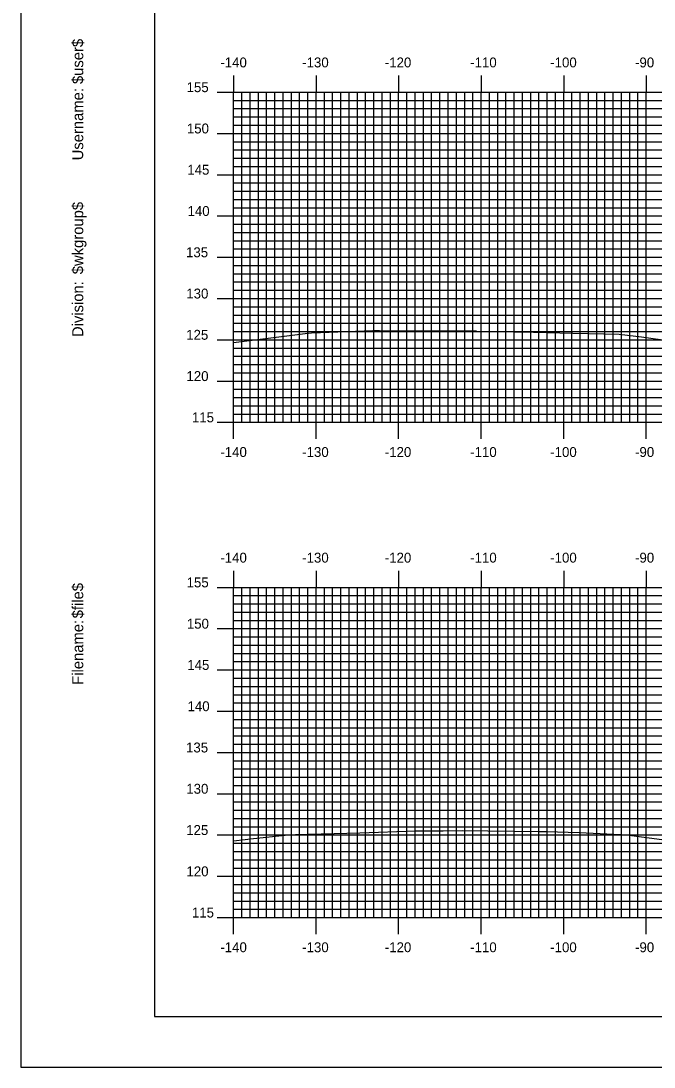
# Model space of a CAD drawing. Extents: x 854508 to 854851, y 364661 to 364881.
# Drawn here: x 854508 to 854584.8, y 364661.3 to 364788 of the extents above; entities that cross this region are included whole.
import ezdxf

# ---------------------------------------------------------------- set-up
doc = ezdxf.new("R2010")
doc.units = 0
for name, color, linetype in [('BORDER', 7, 'Continuous'), ('H_V ANNOTATION', 7, 'Continuous'), ('M_Roadway_Centerline', 7, 'Continuous'), ('MAJOR', 7, 'Continuous'), ('MINOR', 7, 'Continuous'), ('PLOT BOUNDARY', 7, 'Continuous'), ('S_Roadway_Centerline', 7, 'Continuous')]:
    doc.layers.add(name, color=color, linetype=linetype)

msp = doc.modelspace()

# ---------------------------------------------------------------- linework, layer by layer
at = {"layer": 'BORDER'}
msp.add_lwpolyline([(854524.23, 364667.37), (854844.23, 364667.37), (854844.23, 364877.37), (854524.23, 364877.37)], close=True, dxfattribs=at)
at = {"layer": 'MAJOR'}
for p, q in [((854533.83, 364781.37), (854533.83, 364779.37)), ((854543.83, 364781.37), (854543.83, 364779.37)), ((854553.83, 364781.37), (854553.83, 364779.37)), ((854563.83, 364781.37), (854563.83, 364779.37)), ((854573.83, 364781.37), (854573.83, 364779.37)), ((854583.83, 364781.37), (854583.83, 364779.37)), ((854531.83, 364779.37), (854533.83, 364779.37)), ((854533.83, 364779.37), (854813.83, 364779.37)), ((854533.83, 364739.37), (854533.83, 364779.37)), ((854533.83, 364739.37), (854533.83, 364779.37)), ((854533.83, 364779.37), (854813.83, 364779.37)), ((854543.83, 364739.37), (854543.83, 364779.37)), ((854553.83, 364739.37), (854553.83, 364779.37)), ((854563.83, 364739.37), (854563.83, 364779.37)), ((854573.83, 364739.37), (854573.83, 364779.37)), ((854583.83, 364739.37), (854583.83, 364779.37)), ((854531.83, 364774.37), (854533.83, 364774.37)), ((854533.83, 364774.37), (854813.83, 364774.37)), ((854531.83, 364769.37), (854533.83, 364769.37)), ((854533.83, 364769.37), (854813.83, 364769.37)), ((854531.83, 364764.37), (854533.83, 364764.37)), ((854533.83, 364764.37), (854813.83, 364764.37)), ((854531.83, 364759.37), (854533.83, 364759.37)), ((854533.83, 364759.37), (854813.83, 364759.37)), ((854531.83, 364754.37), (854533.83, 364754.37)), ((854533.83, 364754.37), (854813.83, 364754.37)), ((854531.83, 364749.37), (854533.83, 364749.37)), ((854533.83, 364749.37), (854813.83, 364749.37)), ((854531.83, 364744.37), (854533.83, 364744.37)), ((854533.83, 364744.37), (854813.83, 364744.37)), ((854531.83, 364739.37), (854533.83, 364739.37)), ((854533.83, 364739.37), (854813.83, 364739.37)), ((854533.83, 364739.37), (854813.83, 364739.37)), ((854533.83, 364737.37), (854533.83, 364739.37)), ((854543.83, 364737.37), (854543.83, 364739.37)), ((854553.83, 364737.37), (854553.83, 364739.37)), ((854563.83, 364737.37), (854563.83, 364739.37)), ((854573.83, 364737.37), (854573.83, 364739.37)), ((854583.83, 364737.37), (854583.83, 364739.37)), ((854533.83, 364721.37), (854533.83, 364719.37)), ((854543.83, 364721.37), (854543.83, 364719.37)), ((854553.83, 364721.37), (854553.83, 364719.37)), ((854563.83, 364721.37), (854563.83, 364719.37)), ((854573.83, 364721.37), (854573.83, 364719.37)), ((854583.83, 364721.37), (854583.83, 364719.37)), ((854531.83, 364719.37), (854533.83, 364719.37)), ((854533.83, 364719.37), (854813.83, 364719.37)), ((854533.83, 364679.37), (854533.83, 364719.37)), ((854533.83, 364679.37), (854533.83, 364719.37)), ((854533.83, 364719.37), (854813.83, 364719.37)), ((854543.83, 364679.37), (854543.83, 364719.37)), ((854553.83, 364679.37), (854553.83, 364719.37)), ((854563.83, 364679.37), (854563.83, 364719.37)), ((854573.83, 364679.37), (854573.83, 364719.37)), ((854583.83, 364679.37), (854583.83, 364719.37)), ((854531.83, 364714.37), (854533.83, 364714.37)), ((854533.83, 364714.37), (854813.83, 364714.37)), ((854531.83, 364709.37), (854533.83, 364709.37)), ((854533.83, 364709.37), (854813.83, 364709.37)), ((854531.83, 364704.37), (854533.83, 364704.37)), ((854533.83, 364704.37), (854813.83, 364704.37)), ((854531.83, 364699.37), (854533.83, 364699.37)), ((854533.83, 364699.37), (854813.83, 364699.37)), ((854531.83, 364694.37), (854533.83, 364694.37)), ((854533.83, 364694.37), (854813.83, 364694.37)), ((854531.83, 364689.37), (854533.83, 364689.37)), ((854533.83, 364689.37), (854813.83, 364689.37)), ((854531.83, 364684.37), (854533.83, 364684.37)), ((854533.83, 364684.37), (854813.83, 364684.37)), ((854531.83, 364679.37), (854533.83, 364679.37)), ((854533.83, 364679.37), (854813.83, 364679.37)), ((854533.83, 364679.37), (854813.83, 364679.37)), ((854533.83, 364677.37), (854533.83, 364679.37)), ((854543.83, 364677.37), (854543.83, 364679.37)), ((854553.83, 364677.37), (854553.83, 364679.37)), ((854563.83, 364677.37), (854563.83, 364679.37)), ((854573.83, 364677.37), (854573.83, 364679.37)), ((854583.83, 364677.37), (854583.83, 364679.37))]:
    msp.add_line(p, q, dxfattribs=at)
at = {"layer": 'MINOR'}
for p, q in [((854533.83, 364778.37), (854813.83, 364778.37)), ((854533.83, 364778.37), (854535.84, 364778.37)), ((854534.83, 364739.37), (854534.83, 364779.37)), ((854535.83, 364739.37), (854535.83, 364779.37)), ((854536.83, 364739.37), (854536.83, 364779.37)), ((854537.83, 364739.37), (854537.83, 364779.37)), ((854538.83, 364739.37), (854538.83, 364779.37)), ((854539.83, 364739.37), (854539.83, 364779.37)), ((854540.83, 364739.37), (854540.83, 364779.37)), ((854541.83, 364739.37), (854541.83, 364779.37)), ((854542.83, 364739.37), (854542.83, 364779.37)), ((854544.83, 364739.37), (854544.83, 364779.37)), ((854545.83, 364739.37), (854545.83, 364779.37)), ((854546.83, 364739.37), (854546.83, 364779.37)), ((854547.83, 364739.37), (854547.83, 364779.37)), ((854548.83, 364739.37), (854548.83, 364779.37)), ((854549.83, 364739.37), (854549.83, 364779.37)), ((854550.83, 364739.37), (854550.83, 364779.37)), ((854551.83, 364739.37), (854551.83, 364779.37)), ((854552.83, 364739.37), (854552.83, 364779.37)), ((854554.83, 364739.37), (854554.83, 364779.37)), ((854555.83, 364739.37), (854555.83, 364779.37)), ((854556.83, 364739.37), (854556.83, 364779.37)), ((854557.83, 364739.37), (854557.83, 364779.37)), ((854558.83, 364739.37), (854558.83, 364779.37)), ((854559.83, 364739.37), (854559.83, 364779.37)), ((854560.83, 364739.37), (854560.83, 364779.37)), ((854561.83, 364739.37), (854561.83, 364779.37)), ((854562.83, 364739.37), (854562.83, 364779.37)), ((854564.83, 364739.37), (854564.83, 364779.37)), ((854565.83, 364739.37), (854565.83, 364779.37)), ((854566.83, 364739.37), (854566.83, 364779.37)), ((854567.83, 364739.37), (854567.83, 364779.37)), ((854568.83, 364739.37), (854568.83, 364779.37)), ((854569.83, 364739.37), (854569.83, 364779.37)), ((854570.83, 364739.37), (854570.83, 364779.37)), ((854571.83, 364739.37), (854571.83, 364779.37)), ((854572.83, 364739.37), (854572.83, 364779.37)), ((854574.83, 364739.37), (854574.83, 364779.37)), ((854575.83, 364739.37), (854575.83, 364779.37)), ((854576.83, 364739.37), (854576.83, 364779.37)), ((854577.83, 364739.37), (854577.83, 364779.37)), ((854578.83, 364739.37), (854578.83, 364779.37)), ((854579.83, 364739.37), (854579.83, 364779.37)), ((854580.83, 364739.37), (854580.83, 364779.37)), ((854581.83, 364739.37), (854581.83, 364779.37)), ((854582.83, 364739.37), (854582.83, 364779.37)), ((854533.83, 364777.37), (854813.83, 364777.37)), ((854533.83, 364777.37), (854535.84, 364777.37)), ((854533.83, 364776.37), (854813.83, 364776.37)), ((854533.83, 364776.37), (854535.84, 364776.37)), ((854533.83, 364775.37), (854813.83, 364775.37)), ((854533.83, 364775.37), (854535.84, 364775.37)), ((854533.83, 364773.37), (854813.83, 364773.37)), ((854533.83, 364773.37), (854535.84, 364773.37)), ((854533.83, 364772.37), (854813.83, 364772.37)), ((854533.83, 364772.37), (854535.84, 364772.37)), ((854533.83, 364771.37), (854813.83, 364771.37)), ((854533.83, 364771.37), (854535.84, 364771.37)), ((854533.83, 364770.37), (854813.83, 364770.37)), ((854533.83, 364770.37), (854535.84, 364770.37)), ((854533.83, 364768.37), (854813.83, 364768.37)), ((854533.83, 364768.37), (854535.84, 364768.37)), ((854533.83, 364767.37), (854813.83, 364767.37)), ((854533.83, 364767.37), (854535.84, 364767.37)), ((854533.83, 364766.37), (854813.83, 364766.37)), ((854533.83, 364766.37), (854535.84, 364766.37)), ((854533.83, 364765.37), (854813.83, 364765.37)), ((854533.83, 364765.37), (854535.84, 364765.37)), ((854533.83, 364763.37), (854813.83, 364763.37)), ((854533.83, 364763.37), (854535.84, 364763.37)), ((854533.83, 364762.37), (854813.83, 364762.37)), ((854533.83, 364762.37), (854535.84, 364762.37)), ((854533.83, 364761.37), (854813.83, 364761.37)), ((854533.83, 364761.37), (854535.84, 364761.37)), ((854533.83, 364760.37), (854813.83, 364760.37)), ((854533.83, 364760.37), (854535.84, 364760.37)), ((854533.83, 364758.37), (854813.83, 364758.37)), ((854533.83, 364758.37), (854535.84, 364758.37)), ((854533.83, 364757.37), (854813.83, 364757.37)), ((854533.83, 364757.37), (854535.84, 364757.37)), ((854533.83, 364756.37), (854813.83, 364756.37)), ((854533.83, 364756.37), (854535.84, 364756.37)), ((854533.83, 364755.37), (854813.83, 364755.37)), ((854533.83, 364755.37), (854535.84, 364755.37)), ((854533.83, 364753.37), (854813.83, 364753.37)), ((854533.83, 364753.37), (854535.84, 364753.37)), ((854533.83, 364752.37), (854813.83, 364752.37)), ((854533.83, 364752.37), (854535.84, 364752.37)), ((854533.83, 364751.37), (854813.83, 364751.37)), ((854533.83, 364751.37), (854535.84, 364751.37)), ((854533.83, 364750.37), (854813.83, 364750.37)), ((854533.83, 364750.37), (854535.84, 364750.37)), ((854533.83, 364748.37), (854813.83, 364748.37)), ((854533.83, 364748.37), (854535.84, 364748.37)), ((854533.83, 364747.37), (854813.83, 364747.37)), ((854533.83, 364747.37), (854535.84, 364747.37)), ((854533.83, 364746.37), (854813.83, 364746.37)), ((854533.83, 364746.37), (854535.84, 364746.37)), ((854533.83, 364745.37), (854813.83, 364745.37)), ((854533.83, 364745.37), (854535.84, 364745.37)), ((854533.83, 364743.37), (854813.83, 364743.37)), ((854533.83, 364743.37), (854535.84, 364743.37)), ((854533.83, 364742.37), (854813.83, 364742.37)), ((854533.83, 364742.37), (854535.84, 364742.37)), ((854533.83, 364741.37), (854813.83, 364741.37)), ((854533.83, 364741.37), (854535.84, 364741.37)), ((854533.83, 364740.37), (854813.83, 364740.37)), ((854533.83, 364740.37), (854535.84, 364740.37)), ((854534.83, 364679.37), (854534.83, 364719.37)), ((854535.83, 364679.37), (854535.83, 364719.37)), ((854536.83, 364679.37), (854536.83, 364719.37)), ((854537.83, 364679.37), (854537.83, 364719.37)), ((854538.83, 364679.37), (854538.83, 364719.37)), ((854539.83, 364679.37), (854539.83, 364719.37)), ((854540.83, 364679.37), (854540.83, 364719.37)), ((854541.83, 364679.37), (854541.83, 364719.37)), ((854542.83, 364679.37), (854542.83, 364719.37)), ((854544.83, 364679.37), (854544.83, 364719.37)), ((854545.83, 364679.37), (854545.83, 364719.37)), ((854546.83, 364679.37), (854546.83, 364719.37)), ((854547.83, 364679.37), (854547.83, 364719.37)), ((854548.83, 364679.37), (854548.83, 364719.37)), ((854549.83, 364679.37), (854549.83, 364719.37)), ((854550.83, 364679.37), (854550.83, 364719.37)), ((854551.83, 364679.37), (854551.83, 364719.37)), ((854552.83, 364679.37), (854552.83, 364719.37)), ((854554.83, 364679.37), (854554.83, 364719.37)), ((854555.83, 364679.37), (854555.83, 364719.37)), ((854556.83, 364679.37), (854556.83, 364719.37)), ((854557.83, 364679.37), (854557.83, 364719.37)), ((854558.83, 364679.37), (854558.83, 364719.37)), ((854559.83, 364679.37), (854559.83, 364719.37)), ((854560.83, 364679.37), (854560.83, 364719.37)), ((854561.83, 364679.37), (854561.83, 364719.37)), ((854562.83, 364679.37), (854562.83, 364719.37)), ((854564.83, 364679.37), (854564.83, 364719.37)), ((854565.83, 364679.37), (854565.83, 364719.37)), ((854566.83, 364679.37), (854566.83, 364719.37)), ((854567.83, 364679.37), (854567.83, 364719.37)), ((854568.83, 364679.37), (854568.83, 364719.37)), ((854569.83, 364679.37), (854569.83, 364719.37)), ((854570.83, 364679.37), (854570.83, 364719.37)), ((854571.83, 364679.37), (854571.83, 364719.37)), ((854572.83, 364679.37), (854572.83, 364719.37)), ((854574.83, 364679.37), (854574.83, 364719.37)), ((854575.83, 364679.37), (854575.83, 364719.37)), ((854576.83, 364679.37), (854576.83, 364719.37)), ((854577.83, 364679.37), (854577.83, 364719.37)), ((854578.83, 364679.37), (854578.83, 364719.37)), ((854579.83, 364679.37), (854579.83, 364719.37)), ((854580.83, 364679.37), (854580.83, 364719.37)), ((854581.83, 364679.37), (854581.83, 364719.37)), ((854582.83, 364679.37), (854582.83, 364719.37)), ((854533.83, 364718.37), (854813.83, 364718.37)), ((854533.83, 364718.37), (854535.84, 364718.37)), ((854533.83, 364717.37), (854813.83, 364717.37)), ((854533.83, 364717.37), (854535.84, 364717.37)), ((854533.83, 364716.37), (854813.83, 364716.37)), ((854533.83, 364716.37), (854535.84, 364716.37)), ((854533.83, 364715.37), (854813.83, 364715.37)), ((854533.83, 364715.37), (854535.84, 364715.37)), ((854533.83, 364713.37), (854813.83, 364713.37)), ((854533.83, 364713.37), (854535.84, 364713.37)), ((854533.83, 364712.37), (854813.83, 364712.37)), ((854533.83, 364712.37), (854535.84, 364712.37)), ((854533.83, 364711.37), (854813.83, 364711.37)), ((854533.83, 364711.37), (854535.84, 364711.37)), ((854533.83, 364710.37), (854813.83, 364710.37)), ((854533.83, 364710.37), (854535.84, 364710.37)), ((854533.83, 364708.37), (854813.83, 364708.37)), ((854533.83, 364708.37), (854535.84, 364708.37)), ((854533.83, 364707.37), (854813.83, 364707.37)), ((854533.83, 364707.37), (854535.84, 364707.37)), ((854533.83, 364706.37), (854813.83, 364706.37)), ((854533.83, 364706.37), (854535.84, 364706.37)), ((854533.83, 364705.37), (854813.83, 364705.37)), ((854533.83, 364705.37), (854535.84, 364705.37)), ((854533.83, 364703.37), (854813.83, 364703.37)), ((854533.83, 364703.37), (854535.84, 364703.37)), ((854533.83, 364702.37), (854813.83, 364702.37)), ((854533.83, 364702.37), (854535.84, 364702.37)), ((854533.83, 364701.37), (854813.83, 364701.37)), ((854533.83, 364701.37), (854535.84, 364701.37)), ((854533.83, 364700.37), (854813.83, 364700.37)), ((854533.83, 364700.37), (854535.84, 364700.37)), ((854533.83, 364698.37), (854813.83, 364698.37)), ((854533.83, 364698.37), (854535.84, 364698.37)), ((854533.83, 364697.37), (854813.83, 364697.37)), ((854533.83, 364697.37), (854535.84, 364697.37)), ((854533.83, 364696.37), (854813.83, 364696.37)), ((854533.83, 364696.37), (854535.84, 364696.37)), ((854533.83, 364695.37), (854813.83, 364695.37)), ((854533.83, 364695.37), (854535.84, 364695.37)), ((854533.83, 364693.37), (854813.83, 364693.37)), ((854533.83, 364693.37), (854535.84, 364693.37)), ((854533.83, 364692.37), (854813.83, 364692.37)), ((854533.83, 364692.37), (854535.84, 364692.37)), ((854533.83, 364691.37), (854813.83, 364691.37)), ((854533.83, 364691.37), (854535.84, 364691.37)), ((854533.83, 364690.37), (854813.83, 364690.37)), ((854533.83, 364690.37), (854535.84, 364690.37)), ((854533.83, 364688.37), (854813.83, 364688.37)), ((854533.83, 364688.37), (854535.84, 364688.37)), ((854533.83, 364687.37), (854813.83, 364687.37)), ((854533.83, 364687.37), (854535.84, 364687.37)), ((854533.83, 364686.37), (854813.83, 364686.37)), ((854533.83, 364686.37), (854535.84, 364686.37)), ((854533.83, 364685.37), (854813.83, 364685.37)), ((854533.83, 364685.37), (854535.84, 364685.37)), ((854533.83, 364683.37), (854813.83, 364683.37)), ((854533.83, 364683.37), (854535.84, 364683.37)), ((854533.83, 364682.37), (854813.83, 364682.37)), ((854533.83, 364682.37), (854535.84, 364682.37)), ((854533.83, 364681.37), (854813.83, 364681.37)), ((854533.83, 364681.37), (854535.84, 364681.37)), ((854533.83, 364680.37), (854813.83, 364680.37)), ((854533.83, 364680.37), (854535.84, 364680.37))]:
    msp.add_line(p, q, dxfattribs=at)
at = {"layer": 'PLOT BOUNDARY'}
msp.add_lwpolyline([(854508.05, 364661.25), (854848.05, 364661.25), (854848.05, 364881.25), (854508.05, 364881.25)], close=True, dxfattribs=at)
at = {"layer": 'S_Roadway_Centerline'}
for points in [[(854533.83, 364749.05), (854541.25, 364749.96), (854542.81, 364750.16), (854542.9, 364750.17), (854543.25, 364750.19), (854544.34, 364750.25), (854550.68, 364750.5), (854551.52, 364750.48), (854563.18, 364750.44), (854563.28, 364750.43), (854570.18, 364750.28), (854574.96, 364750.18), (854580.56, 364750.04), (854583.27, 364749.73), (854590.13, 364748.77)], [(854533.83, 364688.65), (854535.21, 364688.82), (854535.86, 364688.9), (854540.44, 364689.38), (854541.32, 364689.42), (854549.12, 364689.62), (854555.87, 364689.86), (854559.23, 364689.89), (854561.51, 364689.91), (854570.87, 364689.81), (854571.73, 364689.8), (854575.71, 364689.68), (854581.62, 364689.39), (854582.05, 364689.3), (854595.83, 364687.51)]]:
    msp.add_lwpolyline(points, dxfattribs=at)

# ---------------------------------------------------------------- texts
at = {"layer": 'BORDER'}
for s, p in [('$user$', (854515.6, 364780.35)), ('Username:', (854515.6, 364771.11)), ('$wkgroup$', (854515.6, 364757.31)), ('Division:', (854515.6, 364749.7)), ('$file$', (854515.6, 364715.62)), ('Filename:', (854515.6, 364707.57))]:
    msp.add_text(s, height=1.339, rotation=90, dxfattribs=at).set_placement(p)
at = {"layer": 'H_V ANNOTATION'}
for s, p in [('-140', (854532.22, 364782.37)), ('-130', (854542.14, 364782.37)), ('-120', (854552.15, 364782.37)), ('-110', (854562.5, 364782.37)), ('-100', (854572.2, 364782.37)), ('-90', (854582.48, 364782.37)), ('155', (854528.13, 364779.37)), ('150', (854528.16, 364774.37)), ('145', (854528.21, 364769.37)), ('140', (854528.24, 364764.37)), ('135', (854528.06, 364759.37)), ('130', (854528.09, 364754.37)), ('125', (854528.08, 364749.37)), ('120', (854528.11, 364744.37)), ('115', (854528.77, 364739.37)), ('-140', (854532.22, 364735.17)), ('-130', (854542.14, 364735.17)), ('-120', (854552.15, 364735.17)), ('-110', (854562.5, 364735.17)), ('-100', (854572.2, 364735.17)), ('-90', (854582.48, 364735.17)), ('-140', (854532.22, 364722.37)), ('-130', (854542.14, 364722.37)), ('-120', (854552.15, 364722.37)), ('-110', (854562.5, 364722.37)), ('-100', (854572.2, 364722.37)), ('-90', (854582.48, 364722.37)), ('155', (854528.13, 364719.37)), ('150', (854528.16, 364714.37)), ('145', (854528.21, 364709.37)), ('140', (854528.24, 364704.37)), ('135', (854528.06, 364699.37)), ('130', (854528.09, 364694.37)), ('125', (854528.08, 364689.37)), ('120', (854528.11, 364684.37)), ('115', (854528.77, 364679.37)), ('-140', (854532.22, 364675.17)), ('-130', (854542.14, 364675.17)), ('-120', (854552.15, 364675.17)), ('-110', (854562.5, 364675.17)), ('-100', (854572.2, 364675.17)), ('-90', (854582.48, 364675.17))]:
    msp.add_text(s, height=1.2, dxfattribs=at).set_placement(p)
at = {"layer": 'M_Roadway_Centerline'}
for s, p in [('C', (854563.17, 364750.44)), ('L', (854563.18, 364750.43)), ('C', (854561.51, 364689.91)), ('L', (854561.51, 364689.9))]:
    msp.add_text(s, height=0.0146, dxfattribs=at).set_placement(p)
at = {"layer": 'MAJOR'}
for p in [(854533.82, 364739.37), (854533.82, 364679.37)]:
    msp.add_text('-', height=0.012, dxfattribs=at).set_placement(p)

doc.saveas('drawing.dxf')
